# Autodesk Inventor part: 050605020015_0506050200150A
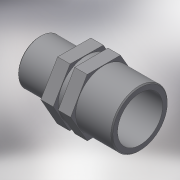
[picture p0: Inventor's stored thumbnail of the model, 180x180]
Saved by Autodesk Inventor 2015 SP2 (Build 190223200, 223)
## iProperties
Created: 2017-05
Part Number: 050605020015_0506050200150A
Material: Generic
Description: PLASSON REDUCING NIPPLE 2"-1.1/2"
Document SubType Name: Modeling
Designer: KIM
Density: 1 g/cm^3
Appearance: Default
Author: KIM
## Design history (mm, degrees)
derived "050605.ipt"
feature "Solid1::050605.ipt"
tag "TaggingFeature1"
body "Solid1"
other parameters: "d0" = 63, "d1" = 59.614, "d5" = 25, "d6" = 6.3, "d8" = 0.63, "d12" = 0, "d14" = 47.803, "d15" = 38.2424, "d16" = 47.6912, "d17" = 21, "d18" = 3.15, "d19" = 63, "d21" = 0, "H_" = 63, "R_" = 59.614, "E_" = 63, "l_" = 25, "R_1" = 47.803, "l_1" = 21
